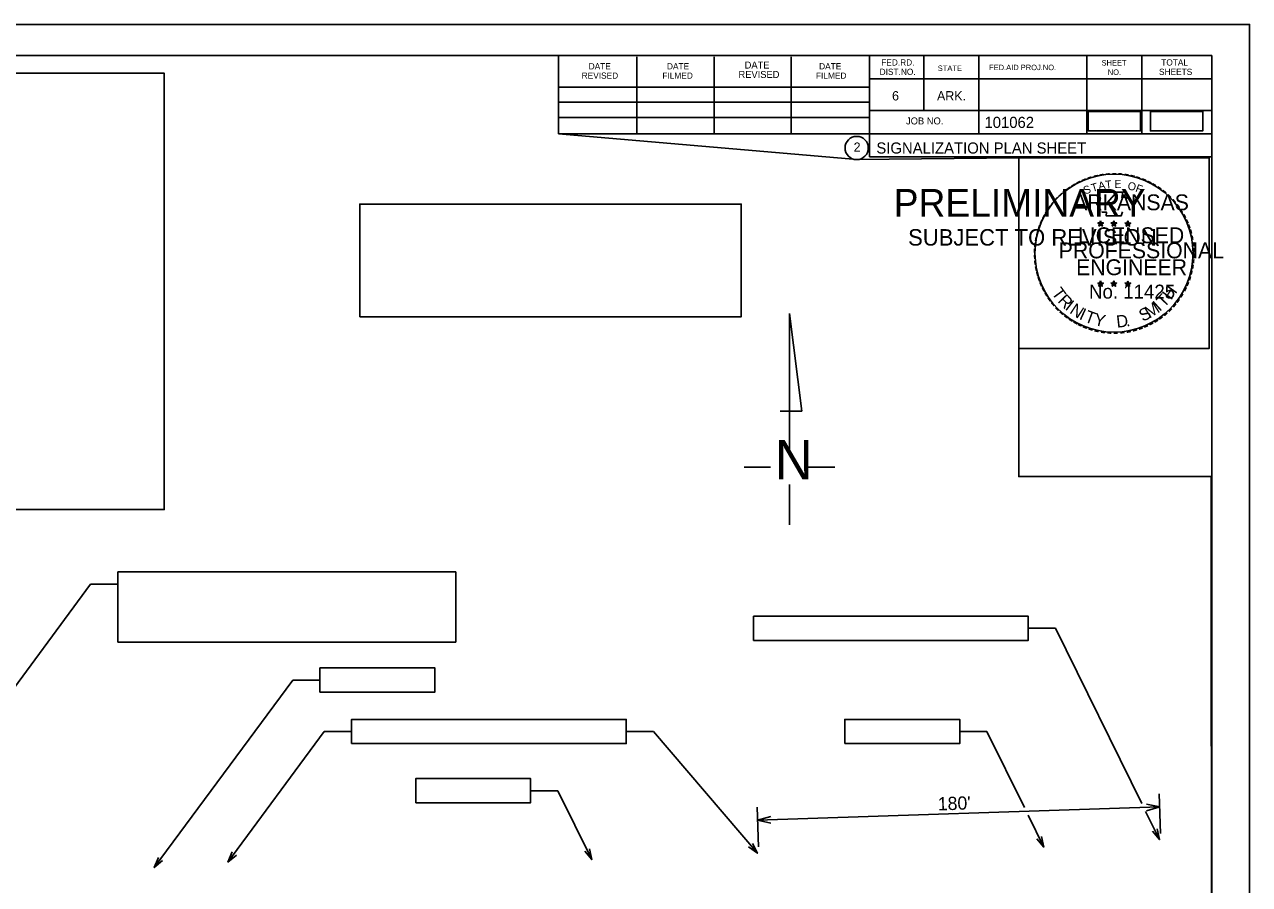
# Model space of a CAD drawing. Extents: x 1736833 to 1738623, y 544707 to 545544.
# Drawn here: x 1738160.6 to 1738623.4, y 545021.7 to 545346.8 of the extents above; entities that cross this region are included whole.
import ezdxf

# ---------------------------------------------------------------- set-up
doc = ezdxf.new("R2010")
doc.units = 0
for name, color, linetype in [('R_Border', 7, 'Continuous'), ('R_Border PE', 7, 'Continuous'), ('R_Border Prem', 7, 'Continuous'), ('R_Dimension', 7, 'Continuous'), ('R_Draft', 7, 'Continuous'), ('R_No Plot', 7, 'Continuous'), ('T_Drafting', 7, 'Continuous')]:
    doc.layers.add(name, color=color, linetype=linetype)

msp = doc.modelspace()

# ---------------------------------------------------------------- linework, layer by layer
at = {"layer": 'R_Border'}
for p, q in [((1737660.6, 545335.14), (1738609.14, 545335.14)), ((1738362.36, 545305.5), (1738362.36, 545335.14)), ((1738391.94, 545305.5), (1738391.94, 545334.54)), ((1738421.22, 545305.5), (1738421.22, 545334.54)), ((1738450.26, 545305.5), (1738450.26, 545334.54)), ((1738479.84, 545335.14), (1738479.84, 545296.74)), ((1738500.36, 545335.14), (1738500.36, 545314.32)), ((1738521.18, 545335.14), (1738521.18, 545305.5)), ((1738561.92, 545335.14), (1738561.92, 545305.5)), ((1738582.74, 545335.14), (1738582.74, 545305.5)), ((1738609.14, 544718.76), (1738609.14, 545335.14)), ((1738609.14, 545326.32), (1738479.84, 545326.32)), ((1738609.14, 545326.38), (1738609.14, 545326.38)), ((1738362.36, 545323.08), (1738479.84, 545323.08)), ((1738362.36, 545317.5), (1738479.84, 545317.5)), ((1738362.36, 545305.5), (1738362.36, 545311.68)), ((1738362.36, 545311.68), (1738479.84, 545311.68)), ((1738609.14, 545314.32), (1738479.84, 545314.32)), ((1738488.72, 545314.32), (1738609.14, 545314.32)), ((1738609.14, 545305.5), (1738362.36, 545305.5)), ((1738479.84, 545296.74), (1738609.14, 545296.74)), ((1738449.66, 545237.63), (1738454.29, 545200.67)), ((1738449.66, 545185.57), (1738449.66, 545237.63)), ((1738446.05, 545200.67), (1738454.29, 545200.67)), ((1738432.54, 545179.43), (1738442.41, 545179.43)), ((1738456.24, 545179.43), (1738466.78, 545179.43)), ((1738449.66, 545157.64), (1738449.66, 545172.95))]:
    msp.add_line(p, q, dxfattribs=at)
msp.add_lwpolyline([(1738042.88, 545163.45), (1738213.45, 545163.45), (1738213.45, 545328.38), (1738042.88, 545328.38)], close=True, dxfattribs=at)
msp.add_circle((1738475, 545300.14), 4.4, dxfattribs=at)
at = {"layer": 'R_Border PE'}
for p, q in [((1738566.12, 545271.82), (1738567.17, 545271.49)), ((1738566.12, 545271.82), (1738566.88, 545271.68)), ((1738566.12, 545271.82), (1738566.83, 545271.45)), ((1738566.52, 545270.6), (1738567.17, 545271.49)), ((1738566.52, 545270.6), (1738566.9, 545271.33)), ((1738566.52, 545270.6), (1738567.16, 545271.25)), ((1738567.17, 545272.58), (1738567.05, 545271.83)), ((1738567.81, 545270.6), (1738567.16, 545271.24)), ((1738567.17, 545271.49), (1738567.17, 545272.58)), ((1738567.17, 545272.58), (1738567.32, 545271.83)), ((1738568.21, 545271.82), (1738567.17, 545271.49)), ((1738567.81, 545270.6), (1738567.17, 545271.49)), ((1738568.21, 545271.82), (1738567.35, 545271.67)), ((1738567.81, 545270.6), (1738567.4, 545271.47)), ((1738568.21, 545271.82), (1738567.6, 545271.51)), ((1738571.13, 545271.82), (1738572.18, 545271.49)), ((1738571.13, 545271.82), (1738571.89, 545271.68)), ((1738571.13, 545271.82), (1738571.84, 545271.45)), ((1738571.53, 545270.6), (1738572.18, 545271.49)), ((1738571.53, 545270.6), (1738571.91, 545271.33)), ((1738571.53, 545270.6), (1738572.17, 545271.25)), ((1738572.18, 545272.58), (1738572.06, 545271.83)), ((1738572.82, 545270.6), (1738572.17, 545271.24)), ((1738572.18, 545271.49), (1738572.18, 545272.58)), ((1738572.18, 545272.58), (1738572.33, 545271.83)), ((1738573.22, 545271.82), (1738572.18, 545271.49)), ((1738572.82, 545270.6), (1738572.18, 545271.49)), ((1738573.22, 545271.82), (1738572.36, 545271.67)), ((1738572.82, 545270.6), (1738572.41, 545271.47)), ((1738573.22, 545271.82), (1738572.61, 545271.51)), ((1738576.42, 545271.78), (1738577.47, 545271.45)), ((1738576.42, 545271.78), (1738577.18, 545271.65)), ((1738576.42, 545271.78), (1738577.14, 545271.42)), ((1738576.82, 545270.56), (1738577.47, 545271.45)), ((1738576.82, 545270.56), (1738577.2, 545271.29)), ((1738576.82, 545270.56), (1738577.47, 545271.21)), ((1738577.47, 545272.55), (1738577.35, 545271.79)), ((1738577.47, 545271.45), (1738577.47, 545272.55)), ((1738577.47, 545272.55), (1738577.62, 545271.8)), ((1738578.51, 545271.78), (1738577.47, 545271.45)), ((1738578.11, 545270.56), (1738577.47, 545271.45)), ((1738578.11, 545270.56), (1738577.47, 545271.2)), ((1738578.51, 545271.78), (1738577.65, 545271.64)), ((1738578.11, 545270.56), (1738577.7, 545271.43)), ((1738578.51, 545271.78), (1738577.9, 545271.48)), ((1738567.16, 545249.86), (1738567.03, 545249.11)), ((1738567.16, 545248.77), (1738567.16, 545249.86)), ((1738567.16, 545249.86), (1738567.3, 545249.11)), ((1738572.16, 545249.86), (1738572.04, 545249.11)), ((1738572.16, 545248.77), (1738572.16, 545249.86)), ((1738572.16, 545249.86), (1738572.31, 545249.11)), ((1738577.47, 545249.83), (1738577.34, 545249.08)), ((1738577.47, 545248.74), (1738577.47, 545249.83)), ((1738577.47, 545249.83), (1738577.61, 545249.08)), ((1738566.11, 545249.1), (1738567.16, 545248.77)), ((1738566.11, 545249.1), (1738566.87, 545248.97)), ((1738566.11, 545249.1), (1738566.82, 545248.73)), ((1738566.51, 545247.88), (1738567.16, 545248.77)), ((1738566.51, 545247.88), (1738566.89, 545248.61)), ((1738566.51, 545247.88), (1738567.15, 545248.53)), ((1738567.8, 545247.88), (1738567.15, 545248.52)), ((1738568.2, 545249.1), (1738567.16, 545248.77)), ((1738567.8, 545247.88), (1738567.16, 545248.77)), ((1738568.2, 545249.1), (1738567.34, 545248.95)), ((1738567.8, 545247.88), (1738567.39, 545248.75)), ((1738568.2, 545249.1), (1738567.59, 545248.79)), ((1738571.12, 545249.1), (1738572.16, 545248.77)), ((1738571.12, 545249.1), (1738571.88, 545248.97)), ((1738571.12, 545249.1), (1738571.83, 545248.73)), ((1738571.52, 545247.88), (1738572.16, 545248.77)), ((1738571.52, 545247.88), (1738571.89, 545248.61)), ((1738571.52, 545247.88), (1738572.16, 545248.53)), ((1738573.21, 545249.1), (1738572.16, 545248.77)), ((1738572.8, 545247.88), (1738572.16, 545248.77)), ((1738572.8, 545247.88), (1738572.16, 545248.52)), ((1738573.21, 545249.1), (1738572.35, 545248.95)), ((1738572.8, 545247.88), (1738572.39, 545248.75)), ((1738573.21, 545249.1), (1738572.59, 545248.79)), ((1738576.42, 545249.07), (1738577.47, 545248.74)), ((1738576.42, 545249.07), (1738577.18, 545248.94)), ((1738576.42, 545249.07), (1738577.13, 545248.7)), ((1738576.82, 545247.85), (1738577.47, 545248.74)), ((1738576.82, 545247.85), (1738577.2, 545248.58)), ((1738576.82, 545247.85), (1738577.46, 545248.5)), ((1738578.1, 545247.85), (1738577.46, 545248.49)), ((1738578.51, 545249.07), (1738577.47, 545248.74)), ((1738578.1, 545247.85), (1738577.47, 545248.74)), ((1738578.51, 545249.07), (1738577.65, 545248.92)), ((1738578.1, 545247.85), (1738577.69, 545248.72)), ((1738578.51, 545249.07), (1738577.89, 545248.76))]:
    msp.add_line(p, q, dxfattribs=at)
for points in [[(1738566.25, 545283.45), (1738567.05, 545280.97)], [(1738576.78, 545280.69), (1738577.2, 545281.54), (1738575.15, 545281.47), (1738575.59, 545283.45), (1738566.25, 545283.45)], [(1738567.72, 545276.18), (1738567.72, 545275.92), (1738569.41, 545275.87), (1738569.25, 545274.45), (1738574.86, 545274.45), (1738575.46, 545276.06)], [(1738567.17, 545272.58), (1738567.81, 545270.6), (1738566.12, 545271.82), (1738568.21, 545271.82), (1738566.52, 545270.6), (1738567.17, 545272.58)], [(1738572.18, 545272.58), (1738572.82, 545270.6), (1738571.13, 545271.82), (1738573.22, 545271.82), (1738571.53, 545270.6), (1738572.18, 545272.58)], [(1738577.47, 545272.55), (1738578.11, 545270.56), (1738576.42, 545271.78), (1738578.51, 545271.78), (1738576.82, 545270.56), (1738577.47, 545272.55)], [(1738567.16, 545249.86), (1738567.8, 545247.88), (1738566.11, 545249.1), (1738568.2, 545249.1), (1738566.51, 545247.88), (1738567.16, 545249.86)], [(1738572.16, 545249.86), (1738572.8, 545247.88), (1738571.12, 545249.1), (1738573.21, 545249.1), (1738571.52, 545247.88), (1738572.16, 545249.86)], [(1738577.47, 545249.83), (1738578.1, 545247.85), (1738576.42, 545249.07), (1738578.51, 545249.07), (1738576.82, 545247.85), (1738577.47, 545249.83)]]:
    msp.add_lwpolyline(points, dxfattribs=at)
for centre, radius in [((1738567.17, 545271.48), 0.517), ((1738567.17, 545271.48), 0.434), ((1738567.17, 545271.48), 0.347), ((1738567.17, 545271.48), 0.297), ((1738567.17, 545271.48), 0.224), ((1738567.17, 545271.48), 0.149), ((1738567.17, 545271.48), 0.0889), ((1738572.18, 545271.48), 0.517), ((1738572.18, 545271.48), 0.434), ((1738572.18, 545271.48), 0.347), ((1738572.18, 545271.48), 0.297), ((1738572.18, 545271.48), 0.224), ((1738572.18, 545271.48), 0.149), ((1738572.18, 545271.48), 0.0889), ((1738577.47, 545271.45), 0.517), ((1738577.47, 545271.45), 0.434), ((1738577.47, 545271.45), 0.347), ((1738577.47, 545271.45), 0.297), ((1738577.47, 545271.45), 0.224), ((1738577.47, 545271.45), 0.149), ((1738577.47, 545271.45), 0.0889), ((1738567.15, 545248.76), 0.517), ((1738567.15, 545248.76), 0.434), ((1738567.15, 545248.76), 0.347), ((1738567.15, 545248.76), 0.297), ((1738567.15, 545248.76), 0.224), ((1738567.15, 545248.76), 0.149), ((1738567.15, 545248.76), 0.0889), ((1738572.16, 545248.76), 0.517), ((1738572.16, 545248.76), 0.434), ((1738572.16, 545248.76), 0.347), ((1738572.16, 545248.76), 0.297), ((1738572.16, 545248.76), 0.224), ((1738572.16, 545248.76), 0.149), ((1738572.16, 545248.76), 0.0889), ((1738577.46, 545248.73), 0.517), ((1738577.46, 545248.73), 0.434), ((1738577.46, 545248.73), 0.347), ((1738577.46, 545248.73), 0.297), ((1738577.46, 545248.73), 0.224), ((1738577.46, 545248.73), 0.149), ((1738577.46, 545248.73), 0.0889)]:
    msp.add_circle(centre, radius, dxfattribs=at)
at = {"layer": 'R_Dimension'}
for p, q in [((1738589.32, 545056.05), (1738589.82, 545041.06)), ((1738437.4, 545050.99), (1738437.9, 545036)), ((1738437.57, 545045.99), (1738589.49, 545051.06))]:
    msp.add_line(p, q, dxfattribs=at)
for points in [[(1738584.45, 545052.14), (1738589.49, 545051.06), (1738584.53, 545049.64)], [(1738442.53, 545047.41), (1738437.57, 545045.99), (1738442.61, 545044.91)]]:
    msp.add_lwpolyline(points, dxfattribs=at)
at = {"layer": 'R_Draft'}
for points in [[(1737660.6, 545335.14), (1738362.36, 545335.14), (1738362.36, 545305.5), (1738475, 545295.74), (1738536.2, 545296.37), (1738536.2, 545224.37), (1738536.2, 545185.59), (1738536.2, 545175.9), (1738608.92, 545175.9), (1738609.14, 544767.79), (1738408.07, 544767.79), (1738257.64, 544767.79), (1738257.64, 544719.22), (1737660.6, 544718.76)], [(1738562.47, 545313.88), (1738582.22, 545313.88), (1738582.22, 545306.59), (1738562.47, 545306.59)], [(1738585.98, 545313.88), (1738605.73, 545313.88), (1738605.73, 545306.59), (1738585.98, 545306.59)]]:
    msp.add_lwpolyline(points, close=True, dxfattribs=at)
at = {"layer": 'R_No Plot'}
for p, q in [((1737623.4, 545346.82), (1738623.4, 545346.82)), ((1738535.97, 545227.69), (1738535.97, 545227.69))]:
    msp.add_line(p, q, dxfattribs=at)
for points in [[(1737623.38, 545346.82), (1738623.4, 545346.82), (1738623.4, 544706.81), (1737623.38, 544706.81)], [(1738536.2, 545296.37), (1738608.2, 545296.37), (1738608.2, 545224.37), (1738536.2, 545224.37)]]:
    msp.add_lwpolyline(points, close=True, dxfattribs=at)
msp.add_circle((1738572.2, 545260.37), 29.86, dxfattribs=at)
at = {"layer": 'T_Drafting'}
for p, q in [((1738133.29, 545064.35), (1738185.6, 545135.24)), ((1738185.6, 545135.24), (1738195.9, 545135.24)), ((1738539.82, 545118.6), (1738550.12, 545118.6)), ((1738582.69, 545052.33), (1738550.12, 545118.6)), ((1738209.64, 545028.13), (1738261.95, 545099.02)), ((1738261.95, 545099.02), (1738272.25, 545099.02)), ((1738237.48, 545030.23), (1738273.88, 545079.56)), ((1738273.88, 545079.56), (1738284.18, 545079.56)), ((1738387.92, 545079.56), (1738398.22, 545079.56)), ((1738437.49, 545033.53), (1738398.22, 545079.56)), ((1738513.93, 545079.56), (1738524.23, 545079.56)), ((1738538.34, 545050.85), (1738524.23, 545079.56)), ((1738351.84, 545057.19), (1738362.14, 545057.19)), ((1738374.94, 545031.16), (1738362.14, 545057.19)), ((1738545.7, 545035.88), (1738539.79, 545047.9)), ((1738589.4, 545038.69), (1738584.15, 545049.38))]:
    msp.add_line(p, q, dxfattribs=at)
for points in [[(1738562.47, 545306.59), (1738582.22, 545306.59), (1738582.22, 545313.88), (1738562.47, 545313.88)], [(1738585.98, 545306.59), (1738605.73, 545306.59), (1738605.73, 545313.88), (1738585.98, 545313.88)], [(1738287.28, 545236.37), (1738431.37, 545236.37), (1738431.37, 545278.91), (1738287.28, 545278.91)], [(1738195.9, 545113.39), (1738323.51, 545113.39), (1738323.51, 545139.87), (1738195.9, 545139.87)], [(1738436.08, 545113.98), (1738539.82, 545113.98), (1738539.82, 545123.1), (1738436.08, 545123.1)], [(1738272.25, 545094.46), (1738315.66, 545094.46), (1738315.66, 545103.58), (1738272.25, 545103.58)], [(1738284.18, 545075), (1738387.92, 545075), (1738387.92, 545084.12), (1738284.18, 545084.12)], [(1738470.52, 545075), (1738513.93, 545075), (1738513.93, 545084.12), (1738470.52, 545084.12)], [(1738308.44, 545052.63), (1738351.84, 545052.63), (1738351.84, 545061.75), (1738308.44, 545061.75)]]:
    msp.add_lwpolyline(points, close=True, dxfattribs=at)
for points in [[(1738588.53, 545042.72), (1738589.4, 545038.69), (1738586.74, 545041.84)], [(1738435.65, 545037.22), (1738437.49, 545033.53), (1738434.13, 545035.93)], [(1738544.83, 545039.91), (1738545.7, 545035.88), (1738543.03, 545039.03)], [(1738240.66, 545032.86), (1738237.48, 545030.23), (1738239.05, 545034.05)], [(1738374.07, 545035.19), (1738374.94, 545031.16), (1738372.27, 545034.31)], [(1738212.82, 545030.75), (1738209.64, 545028.13), (1738211.21, 545031.94)]]:
    msp.add_lwpolyline(points, dxfattribs=at)

# ---------------------------------------------------------------- texts
at = {"layer": 'R_Border'}
for s, height, p in [('FED.RD.', 2.346, (1738484.28, 545331.3)), ('SHEET', 2.052, (1738567.5, 545331.3)), ('TOTAL', 2.346, (1738590.06, 545331.3)), ('REVISED', 2.346, (1738371.12, 545326.32)), ('DATE', 2.346, (1738373.76, 545329.86)), ('FILMED', 2.346, (1738401.6, 545326.32)), ('DATE', 2.346, (1738403.34, 545329.86)), ('REVISED', 2.638, (1738430.34, 545326.62)), ('DATE', 2.638, (1738432.68, 545330.16)), ('FILMED', 2.346, (1738459.62, 545326.32)), ('DATE', 2.346, (1738460.82, 545329.86)), ('DIST.NO.', 2.346, (1738483.68, 545327.76)), ('STATE', 2.052, (1738505.64, 545329.26)), ('FED.AID PROJ.NO.', 2.052, (1738525.02, 545329.56)), ('NO.', 2.052, (1738569.84, 545327.76)), ('SHEETS', 2.346, (1738589.22, 545327.76)), ('6', 3.52, (1738488.36, 545318.1)), ('ARK.', 3.517, (1738505.34, 545318.1)), ('JOB NO.', 2.638, (1738493.64, 545309.04)), ('101062', 4.2, (1738523.27, 545307.72)), ('2', 3.52, (1738473.85, 545298.69)), ('SIGNALIZATION PLAN SHEET', 4.2, (1738482.43, 545298.03)), ('N', 14.89, (1738444.02, 545174.84))]:
    msp.add_text(s, height=height, dxfattribs=at).set_placement(p)
at = {"layer": 'R_Border PE'}
for s, height, rotation, p in [('-', 4.8, 28.7918, (1738558.69, 545285.08)), ('-', 4.8, 24.3072, (1738560.59, 545286.03)), ('-', 4.8, 19.1761, (1738562.49, 545286.83)), ('T', 3, 16.4036, (1738564.05, 545283.48)), ('-', 4.8, 13.6302, (1738564.74, 545287.56)), ('A', 3, 11.2132, (1738566.53, 545284.23)), ('-', 4.8, 10.2193, (1738566.77, 545288.04)), ('T', 3, 6.0228, (1738569.08, 545284.73)), ('-', 4.8, 5.8968, (1738568.96, 545288.37)), ('-', 4.8, 0.1862, (1738571.28, 545288.59)), ('E', 3, 0.8323, (1738572.39, 545285.06)), ('-', 4.8, 357.743, (1738573.44, 545288.55)), ('-', 4.8, 352.1617, (1738575.68, 545288.38)), ('O', 3, 350.4515, (1738577.2, 545284.43)), ('-', 4.8, 347.2049, (1738577.83, 545288.04)), ('-', 4.8, 342.3362, (1738579.74, 545287.58)), ('-', 4.8, 337.8551, (1738581.94, 545286.91)), ('-', 4.8, 334.1211, (1738583.84, 545286.09)), ('-', 4.8, 329.6409, (1738585.57, 545285.24)), ('-', 4.8, 42.9622, (1738552.44, 545280.4)), ('-', 4.8, 38.9507, (1738553.73, 545281.65)), ('-', 4.8, 36.2317, (1738555.16, 545282.78)), ('-', 4.8, 34.0636, (1738556.9, 545283.97)), ('S', 3, 21.594, (1738561.31, 545282.49)), ('F', 3, 340.0707, (1738580.07, 545283.75)), ('-', 4.8, 325.8627, (1738587.5, 545284.16)), ('-', 4.8, 320.5297, (1738589.33, 545282.88)), ('-', 4.8, 315.5786, (1738591.13, 545281.42)), ('-', 4.8, 54.2325, (1738548.64, 545275.8)), ('-', 4.8, 50.6142, (1738549.88, 545277.5)), ('-', 4.8, 48.4231, (1738551.09, 545278.96)), ('-', 4.8, 309.8797, (1738592.84, 545279.77)), ('-', 4.8, 306.6522, (1738594.41, 545277.96)), ('-', 4.8, 67.7743, (1738545.95, 545270.55)), ('-', 4.8, 62.8713, (1738546.73, 545272.38)), ('-', 4.8, 58.0706, (1738547.67, 545274.22)), ('-', 4.2, 303.6753, (1738595.87, 545276.26)), ('-', 4.8, 299.6684, (1738596.83, 545274.44)), ('-', 4.8, 294.6628, (1738597.8, 545272.6)), ('-', 4.8, 75.461, (1738544.7, 545266.52)), ('-', 4.8, 72.3945, (1738545.3, 545268.66)), ('-', 4.8, 290.5728, (1738598.57, 545270.87)), ('-', 4.8, 285.1233, (1738599.27, 545269.13)), ('-', 4.8, 85.1863, (1738544.08, 545262.3)), ('-', 4.8, 81.2013, (1738544.31, 545264.38)), ('-', 4.8, 280.5493, (1738599.87, 545266.91)), ('-', 4.8, 276.5962, (1738600.36, 545264.6)), ('-', 4.8, 94.1959, (1738544.11, 545258.03)), ('-', 4.8, 89.0622, (1738544.01, 545260.2)), ('-', 4.8, 274.3301, (1738600.54, 545262.44)), ('-', 4.8, 269.9407, (1738600.64, 545260.54)), ('-', 4.8, 98.9479, (1738544.33, 545256.02)), ('-', 4.8, 101.7149, (1738544.73, 545253.83)), ('-', 4.8, 260.9953, (1738600.37, 545256.58)), ('-', 4.8, 263.5172, (1738600.58, 545258.54)), ('-', 4.8, 105.4578, (1738545.22, 545252.04)), ('-', 4.8, 109.0874, (1738545.86, 545250.15)), ('-', 4.8, 252.8681, (1738599.5, 545252.39)), ('-', 4.8, 255.7626, (1738600.04, 545254.55)), ('-', 4.8, 114.0643, (1738546.62, 545248.36)), ('-', 4.8, 115.7289, (1738547.54, 545246.51)), ('-', 4.8, 120.4471, (1738548.61, 545244.75)), ('T', 4.62, 306.0406, (1738548.44, 545245.28)), ('T', 4.62, 46.6444, (1738591.13, 545239.56)), ('H', 4.62, 54.6088, (1738593.8, 545242.39)), ('-', 4.8, 244.6197, (1738598.04, 545248.48)), ('-', 4.8, 247.8887, (1738598.83, 545250.37)), ('-', 4.8, 125.8934, (1738549.82, 545243.06)), ('-', 4.8, 130.7181, (1738551.21, 545241.41)), ('R', 4.62, 314.005, (1738550.72, 545242.14)), ('I', 4.62, 321.9694, (1738553.42, 545239.34)), ('N', 4.62, 326.5002, (1738555.13, 545237.93)), ('M', 4.62, 32.6563, (1738585.59, 545235.58)), ('I', 4.62, 42.1136, (1738589.44, 545238.13)), ('-', 4.8, 231.2538, (1738594.36, 545242.57)), ('-', 4.8, 233.8452, (1738595.65, 545244.26)), ('-', 4.8, 239.0712, (1738596.86, 545246.22)), ('-', 4.8, 134.2238, (1738552.76, 545239.77)), ('-', 4.8, 138.9338, (1738554.33, 545238.38)), ('-', 4.8, 144.6463, (1738556, 545237.16)), ('I', 4.62, 335.3603, (1738558.75, 545235.57)), ('T', 4.62, 339.8912, (1738560.73, 545234.59)), ('Y', 4.62, 347.8556, (1738564.38, 545233.25)), ('D', 4.62, 6.3969, (1738573.34, 545232.18)), ('S', 4.62, 26.9312, (1738583.07, 545234.37)), ('-', 4.8, 215.7363, (1738589.71, 545237.93)), ('-', 4.8, 221.0851, (1738591.36, 545239.35)), ('-', 4.8, 225.7653, (1738592.93, 545240.87)), ('-', 4.8, 148.0898, (1738557.68, 545236.05)), ('-', 4.8, 151.5704, (1738559.42, 545235.08)), ('-', 4.8, 154.6002, (1738560.99, 545234.33)), ('-', 4.8, 158.5612, (1738562.86, 545233.57)), ('-', 4.8, 162.7983, (1738564.92, 545232.93)), ('-', 4.8, 167.5555, (1738567.06, 545232.44)), ('.', 4.62, 13.7642, (1738576.92, 545232.56)), ('-', 4.8, 195.4743, (1738580.68, 545233.23)), ('-', 4.8, 200.7184, (1738582.71, 545233.96)), ('-', 4.8, 204.2516, (1738584.57, 545234.78)), ('-', 4.8, 207.3568, (1738586.44, 545235.73)), ('-', 4.8, 212.2491, (1738588.11, 545236.77)), ('-', 4.8, 173.1155, (1738569.38, 545232.11)), ('-', 4.8, 176.5183, (1738571.62, 545231.95)), ('-', 4.8, 181.5918, (1738573.86, 545232.01)), ('-', 4.8, 185.8167, (1738576.28, 545232.24)), ('-', 4.8, 191.2858, (1738578.49, 545232.63))]:
    msp.add_text(s, height=height, rotation=rotation, dxfattribs=at).set_placement(p)
for s, height, p in [('ARKANSAS', 6, (1738556.8, 545276.59)), ('LICENSED', 6, (1738558.6, 545264.14)), ('DWB', 0.03, (1738567.13, 545271.47)), ('DWB', 0.03, (1738572.14, 545271.47)), ('DWB', 0.03, (1738577.43, 545271.44)), ('PROFESSIONAL', 6, (1738551.33, 545258.43)), ('ENGINEER', 6, (1738557.89, 545252.06)), ('No. 11425', 5.271, (1738562.77, 545243.2)), ('DWB', 0.03, (1738567.12, 545248.75)), ('DWB', 0.03, (1738572.13, 545248.75)), ('DWB', 0.03, (1738577.43, 545248.72))]:
    msp.add_text(s, height=height, dxfattribs=at).set_placement(p)
at = {"layer": 'R_Border Prem'}
for s, height, p in [('PRELIMINARY', 10.5, (1738488.99, 545274.13)), ('SUBJECT TO REVISION', 6.2253, (1738494.42, 545263.24))]:
    msp.add_text(s, height=height, dxfattribs=at).set_placement(p)
at = {"layer": 'R_Dimension'}
msp.add_text("180'", height=5, rotation=1.9094, dxfattribs=at).set_placement((1738505.71, 545049.71))

doc.saveas('drawing.dxf')
